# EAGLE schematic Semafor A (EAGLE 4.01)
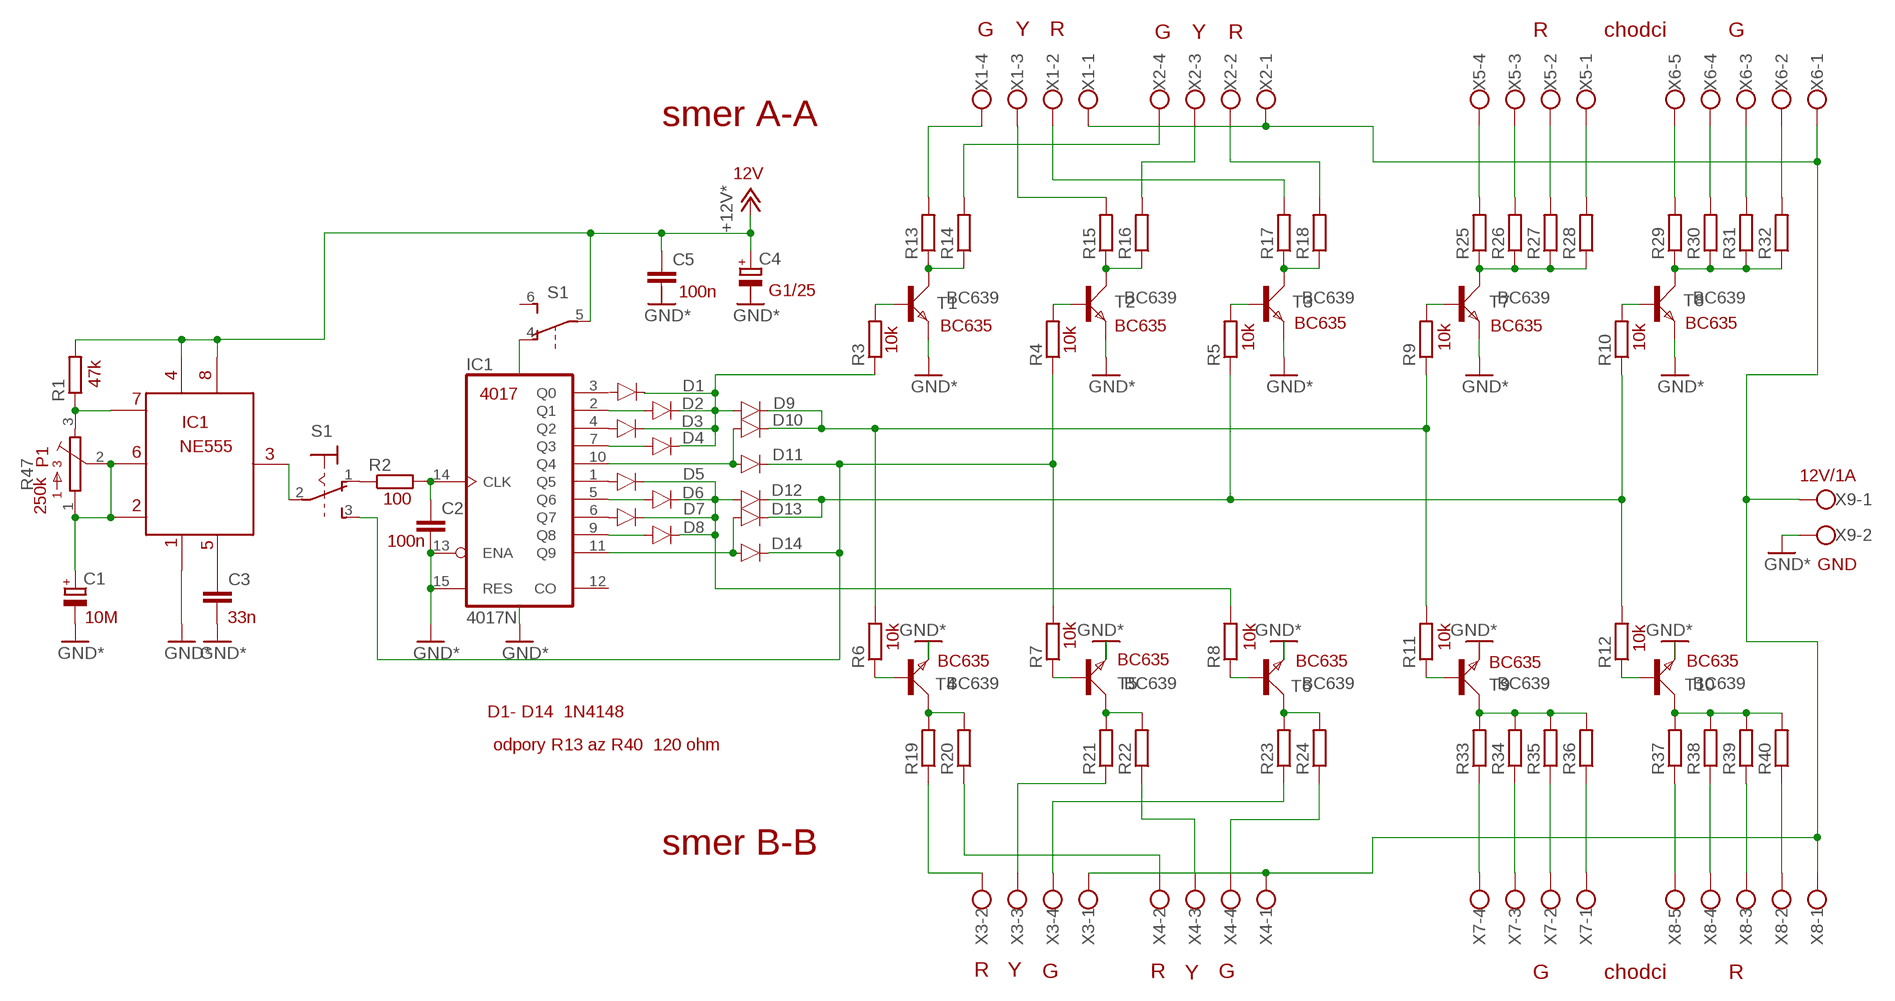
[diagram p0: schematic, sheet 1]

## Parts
C1  CPOL-EUB45181A  [B45181A]
C2  C-EU025-025X050  [C025-025X050]
C3  C-EU025-025X050  [C025-025X050]
C4  CPOL-EUB45181B  [B45181B]
C5  C-EU025-025X050  [C025-025X050]
D1  1N4148/71N4148/7  [1N4148/7]
D2  1N4148/71N4148/7  [1N4148/7]
D3  1N4148/71N4148/7  [1N4148/7]
D4  1N4148/71N4148/7  [1N4148/7]
D5  1N4148/71N4148/7  [1N4148/7]
D6  1N4148/71N4148/7  [1N4148/7]
D7  1N4148/71N4148/7  [1N4148/7]
D8  1N4148/71N4148/7  [1N4148/7]
D9  1N4148/71N4148/7  [1N4148/7]
D10  1N4148/71N4148/7  [1N4148/7]
D11  1N4148/71N4148/7  [1N4148/7]
D12  1N4148/71N4148/7  [1N4148/7]
D13  1N4148/71N4148/7  [1N4148/7]
D14  1N4148/71N4148/7  [1N4148/7]
IC1  4017N  [DIL16]
R1  R-EU_0207/7  [0207/7]
R2  R-EU_0207/7  [0207/7]
R3  R-EU_0207/7  [0207/7]
R4  R-EU_0207/7  [0207/7]
R5  R-EU_0207/7  [0207/7]
R6  R-EU_0207/7  [0207/7]
R7  R-EU_0207/7  [0207/7]
R8  R-EU_0207/7  [0207/7]
R9  R-EU_0207/7  [0207/7]
R10  R-EU_0207/7  [0207/7]
R11  R-EU_0207/7  [0207/7]
R12  R-EU_0207/7  [0207/7]
R13  R-EU_0207/7  [0207/7]
R14  R-EU_0207/7  [0207/7]
R15  R-EU_0207/7  [0207/7]
R16  R-EU_0207/7  [0207/7]
R17  R-EU_0207/7  [0207/7]
R18  R-EU_0207/7  [0207/7]
R19  R-EU_0207/7  [0207/7]
R20  R-EU_0207/7  [0207/7]
R21  R-EU_0207/7  [0207/7]
R22  R-EU_0207/7  [0207/7]
R23  R-EU_0207/7  [0207/7]
R24  R-EU_0207/7  [0207/7]
R25  R-EU_0207/7  [0207/7]
R26  R-EU_0207/7  [0207/7]
R27  R-EU_0207/7  [0207/7]
R28  R-EU_0207/7  [0207/7]
R29  R-EU_0207/7  [0207/7]
R30  R-EU_0207/7  [0207/7]
R31  R-EU_0207/7  [0207/7]
R32  R-EU_0207/7  [0207/7]
R33  R-EU_0207/7  [0207/7]
R34  R-EU_0207/7  [0207/7]
R35  R-EU_0207/7  [0207/7]
R36  R-EU_0207/7  [0207/7]
R37  R-EU_0207/7  [0207/7]
R38  R-EU_0207/7  [0207/7]
R39  R-EU_0207/7  [0207/7]
R40  R-EU_0207/7  [0207/7]
R47  CA9V  [CA9V]
S1  320-938  [320-938]
T1  BC639  [SOT54D]
T2  BC639  [SOT54D]
T3  BC639  [SOT54D]
T4  BC639  [SOT54D]
T5  BC639  [SOT54D]
T6  BC639  [SOT54D]
T7  BC639  [SOT54D]
T8  BC639  [SOT54D]
T9  BC639  [SOT54D]
T10  BC639  [SOT54D]
X1  AK500/4  [AK500/4]
X2  AK500/4  [AK500/4]
X3  AK500/4  [AK500/4]
X4  AK500/4  [AK500/4]
X5  AK500/4  [AK500/4]
X6  AK500/5  [AK500/5]
X7  AK500/4  [AK500/4]
X8  AK500/5  [AK500/5]
X9  AK500/2  [AK500/2]

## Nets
+12V: C4.+ C5.2 R1.2 S1.5(B:P) ; supply symbol labelled +12V*
GND: C1.- C2.1 C3.1 IC1.13(ENA) IC1.15(RES) T1.E T2.E T3.E T4.E T5.E T6.E T7.E T8.E T9.E T10.E X9.2 ; supply symbol labelled GND*
N$1: R2.1 S1.1(1:O)
N$2: C2.2 IC1.14(CLK) R2.2
N$3: D10.P$1 D11.P$1 IC1.10(Q4)
N$4: C1.+ R47.1 R47.2
N$5: D13.P$1 D14.P$1 IC1.11(Q9)
N$6: R1.1 R47.3
N$7: S1.2(1:P)
N$8: R3.2 T1.B
N$9: S1.4(B:O)
N$10: R15.1 R16.1 T2.C
N$11: R17.1 R18.1 T3.C
N$12: D2.P$1 IC1.2(Q1)
N$13: D3.P$1 IC1.4(Q2)
N$14: D4.P$1 IC1.7(Q3)
N$15: D5.P$1 IC1.1(Q5)
N$16: D6.P$1 IC1.5(Q6)
N$17: D7.P$1 IC1.6(Q7)
N$18: D8.P$1 IC1.9(Q8)
N$19: D2.P$2 D3.P$2 D4.P$2 D9.P$1 R3.1
N$20: D9.P$2 D10.P$2 R6.2 R9.1 R11.2
N$21: D12.P$2 D13.P$2 R5.1 R10.1 R12.2
N$22: D5.P$2 D6.P$2 D7.P$2 D8.P$2 D12.P$1 R8.2
N$23: D11.P$2 D14.P$2 R4.1 R7.2 S1.3(1:S)
N$24: R13.2 X1.4
N$25: R5.2 T3.B
N$26: R4.2 T2.B
N$27: R6.1 T4.B
N$28: R7.1 T5.B
N$29: R8.1 T6.B
N$30: R14.2 X2.4
N$31: R15.2 X1.3
N$32: R16.2 X2.3
N$33: R17.2 X1.2
N$34: R9.2 T7.B
N$35: R18.2 X2.2
N$36: R11.1 T9.B
N$37: R12.1 T10.B
N$38: R21.1 X3.3
N$39: R23.1 X3.4
N$40: R13.1 R14.1
N$41: X1.1 X2.1 X3.1 X4.1 X6.1 X8.1 X9.1
N$42: R25.1 R26.1 R27.1 R28.1 T7.C
N$43: R19.2 R20.2 T4.C
N$44: R21.2 R22.2 T5.C
N$45: R10.2 T8.B
N$46: R23.2 R24.2 T6.C
N$47: R29.1 R30.1 R31.1 R32.1 T8.C
N$48: R22.1 X4.3
N$49: R24.1 X4.4
N$51: R33.2 R34.2 R35.2 R36.2 T9.C
N$52: R37.2 R38.2 R39.2 R40.2 T10.C
N$53: R19.1 X3.2
N$54: R20.1 X4.2
N$55: R25.2 X5.4
N$56: R26.2 X5.3
N$57: R27.2 X5.2
N$58: R28.2 X5.1
N$59: R29.2 X6.5
N$60: R30.2 X6.4
N$61: R31.2 X6.3
N$62: R32.2 X6.2
N$63: R40.1 X8.2
N$64: R39.1 X8.3
N$65: R38.1 X8.4
N$66: R37.1 X8.5
N$67: R36.1 X7.1
N$68: R35.1 X7.2
N$69: R34.1 X7.3
N$70: R33.1 X7.4
Unconnected: C3.2 C4.- C5.1 D1.P$1 D1.P$2 IC1.3(Q0) IC1.12(CO) S1.6(B:S) T1.C

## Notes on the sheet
- G | Y | R | G | Y | R | R | chodci | G
- smer A-A
- 12V
- 100n | G1/25
- BC635 | BC635 | BC635 | BC635 | BC635
- 10k | 10k | 10k | 10k | 10k
- 4 | 8
- 47k
- 7 | 4017
- IC1
- NE555
- 6 | 3
- P1
- 12V/1A
- 100
- 250k | 2
- 1 | 5 | 100n
- GND
- 10M | 33n
- 10k | 10k | 10k | 10k | 10k
- BC635 | BC635 | BC635 | BC635 | BC635
- D1- D14  1N4148
- odpory R13 az R40  120 ohm
- smer B-B
- R | Y | G | R | Y | G | G | chodci | R

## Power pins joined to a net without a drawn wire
VDD: IC1.16(VDD)
VSS: IC1.8(VSS)

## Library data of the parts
C1 C4 = rcl:CPOL-EU: POLARIZED CAPACITOR, European symbol
C2 C3 C5 = rcl:C-EU: CAPACITOR, European symbol
D1-D14 = diode1:1N4148/7
IC1 = 40xx:4017: COUNTER/DIVIDER
R1-R40 = rcl:R-EU_: RESISTOR, European symbol
R47 = pot:CA9V: POTENTIOMETER
S1 = switch:320-938: TOGGLE SWITCH distributor RS Components
T1-T10 = transistor-small-signal:BC639: NPN TRANSISTOR
X1-X5 X7 = con-ptr500:AK500/4: CONNECTOR
X6 X8 = con-ptr500:AK500/5: CONNECTOR
X9 = con-ptr500:AK500/2: CONNECTOR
